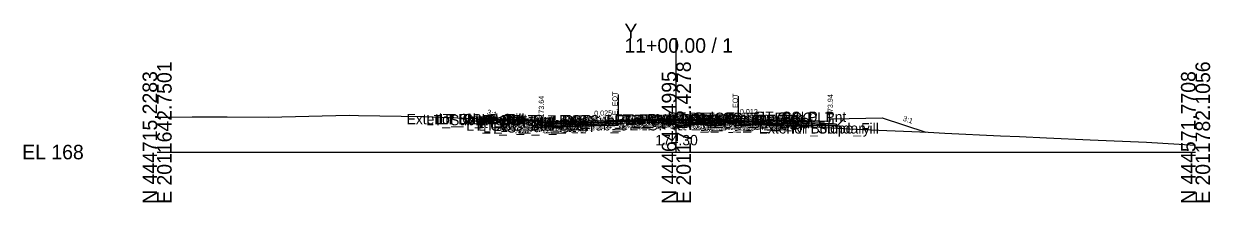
# Model space of a CAD drawing. Extents: x -26 to 3203, y -10 to 9532.
# Drawn here: x -25.7 to 202.8, y 4990.3 to 5024.8 of the extents above; entities that cross this region are included whole.
import ezdxf

# ---------------------------------------------------------------- set-up
doc = ezdxf.new("R2010")
doc.units = 0
for name, color, linetype in [('Default', 7, 'Continuous'), ('Exist CMT Pavement', 7, 'Continuous'), ('Exist Cross Section Cell', 7, 'Continuous'), ('Exist XS Center Line Elevation Label', 7, 'Continuous'), ('Exist XS Ground Line', 7, 'Continuous'), ('Prop CMT Conc Surface', 7, 'Continuous'), ('Prop CMT Concrete Structures', 7, 'Continuous'), ('Prop CMT Pvmt Course 1', 7, 'Continuous'), ('Prop CMT Pvmt Course 1 CG', 7, 'Continuous'), ('Prop CMT Pvmt Course 1 Wedge', 7, 'Continuous'), ('Prop CMT Pvmt Course 2', 7, 'Continuous'), ('Prop CMT Pvmt Course 2 Wedge', 7, 'Continuous'), ('Prop CMT Pvmt Course 3', 7, 'Continuous'), ('Prop CMT Pvmt Surface', 7, 'Continuous'), ('Prop CMT Pvmt Wedge Surface 1', 7, 'Continuous'), ('Prop CMT Pvmt Wedge Surface 2', 7, 'Continuous'), ('Prop CMT Pvmt Wedge Surface 3', 7, 'Continuous'), ('Prop CMT Slope Grass', 7, 'Continuous'), ('Prop CMT Subgrade Earthwork', 7, 'Continuous'), ('Prop XS Hydro Elevations', 7, 'Continuous'), ('Prop XS Label Text', 7, 'Continuous'), ('Prop XS SE Text', 7, 'Continuous'), ('Prop XS Side Slope Text', 7, 'Continuous'), ('Scratch_Level_0', 7, 'Continuous')]:
    doc.layers.add(name, color=color, linetype=linetype)

msp = doc.modelspace()

# ---------------------------------------------------------------- linework, layer by layer
at = {"layer": 'Exist CMT Pavement'}
msp.add_lwpolyline([(88.78, 5006.11), (89.34, 5006.15), (89.79, 5006.17), (90.87, 5006.19), (92.27, 5006.22), (94.36, 5006.26), (95.85, 5006.27), (97.83, 5006.28), (99.28, 5006.3), (100.22, 5006.31), (101.31, 5006.26), (102.91, 5006.2), (104.8, 5006.14), (105.66, 5006.11), (106.57, 5006.07), (107.47, 5006.02), (108.27, 5005.98), (110.14, 5005.9), (111.1, 5005.86), (111.94, 5005.78)], dxfattribs=at)
at = {"layer": 'Exist Cross Section Cell'}
for p, q in [((100, 5000), (100, 5021.96)), ((0, 5000), (100, 5000)), ((100, 5000), (200, 5000))]:
    msp.add_line(p, q, dxfattribs=at)
at = {"layer": 'Exist XS Ground Line'}
msp.add_lwpolyline([(0, 5006.71), (2.64, 5006.72), (6.76, 5006.78), (7.82, 5006.8), (13.47, 5006.8), (21.44, 5006.74), (36.96, 5007.1), (38.76, 5007.07), (51.13, 5006.87), (51.56, 5006.85), (64.13, 5006.35), (72.62, 5006.01), (73.31, 5006), (75.59, 5005.96), (78.67, 5005.98), (81.5, 5006.01), (86.68, 5006.09), (88.76, 5006.11), (89.34, 5006.15), (89.79, 5006.17), (90.87, 5006.19), (92.27, 5006.22), (94.36, 5006.26), (95.85, 5006.27), (97.83, 5006.28), (99.28, 5006.3), (100.22, 5006.31), (101.31, 5006.26), (102.91, 5006.2), (104.8, 5006.14), (105.66, 5006.11), (106.57, 5006.07), (107.47, 5006.02), (108.27, 5005.98), (110.14, 5005.9), (111.1, 5005.86), (111.95, 5005.77), (119.91, 5005.27), (123.03, 5005.08), (134.57, 5004.42), (137.39, 5004.29), (148.51, 5003.82), (151.74, 5003.67), (162.45, 5003.14), (166.09, 5003), (171.32, 5002.75), (179.7, 5002.39), (190.53, 5001.89), (200, 5001.32)], dxfattribs=at)
at = {"layer": 'Prop CMT Conc Surface'}
for points in [[(74, 5005.64), (74, 5006.14), (73.5, 5006.14)], [(76, 5005.77), (74, 5005.64)], [(127.65, 5006.04), (129.65, 5005.94)], [(129.65, 5005.94), (129.65, 5006.44), (130.15, 5006.44)]]:
    msp.add_lwpolyline(points, dxfattribs=at)
at = {"layer": 'Prop CMT Concrete Structures'}
for points in [[(76, 5005.77), (74, 5005.64), (74, 5006.14), (73.5, 5006.14)], [(73.5, 5006.14), (73.5, 5005.12), (76, 5005.18)], [(76, 5005.18), (76, 5005.77)], [(127.65, 5006.04), (129.65, 5005.94), (129.65, 5006.44), (130.15, 5006.44)], [(130.15, 5006.44), (130.15, 5005.43), (127.65, 5005.46)], [(127.65, 5005.46), (127.65, 5006.04)]]:
    msp.add_lwpolyline(points, dxfattribs=at)
at = {"layer": 'Prop CMT Pvmt Course 1'}
for points in [[(100, 5006.37), (76, 5005.77)], [(76, 5005.52), (88.76, 5005.83)], [(76, 5005.77), (76, 5005.52)], [(88.76, 5005.96), (100, 5006.24)], [(88.76, 5005.83), (88.76, 5005.96)], [(100, 5006.37), (127.65, 5006.04)], [(100, 5006.12), (100, 5006.37)], [(100, 5006.12), (100, 5006.37)], [(111.96, 5006.1), (100, 5006.24)], [(100, 5006.24), (100, 5006.12), (100, 5006.12)], [(100, 5006.24), (100, 5006.12), (100, 5006.12)], [(111.96, 5005.98), (111.96, 5006.1)], [(113.07, 5005.96), (111.96, 5005.98)], [(127.65, 5006.04), (127.65, 5005.79)]]:
    msp.add_lwpolyline(points, dxfattribs=at)
at = {"layer": 'Prop CMT Pvmt Course 1 CG'}
for points in [[(76, 5005.18), (73, 5005.11), (72.66, 5004.77)], [(76, 5004.85), (76, 5005.18)], [(127.65, 5005.46), (130.65, 5005.43), (130.99, 5005.09)], [(127.65, 5005.13), (127.65, 5005.46)], [(130.99, 5005.09), (127.65, 5005.13)], [(72.66, 5004.77), (76, 5004.85)]]:
    msp.add_lwpolyline(points, dxfattribs=at)
at = {"layer": 'Prop CMT Pvmt Course 1 Wedge'}
for points in [[(100, 5006.24), (88.76, 5005.96)], [(100, 5006.24), (111.96, 5006.1)]]:
    msp.add_lwpolyline(points, dxfattribs=at)
at = {"layer": 'Prop CMT Pvmt Course 2'}
for points in [[(88.76, 5005.83), (76, 5005.52)], [(76, 5005.52), (76, 5005.18)], [(76, 5005.18), (88.76, 5005.5)], [(88.76, 5005.5), (88.76, 5005.83)], [(111.96, 5005.64), (111.96, 5005.98)], [(111.96, 5005.98), (127.65, 5005.79)], [(113.07, 5005.63), (111.96, 5005.64)], [(127.65, 5005.79), (127.65, 5005.46)]]:
    msp.add_lwpolyline(points, dxfattribs=at)
at = {"layer": 'Prop CMT Pvmt Course 2 Wedge'}
msp.add_lwpolyline([(107.33, 5006.03), (111.96, 5005.98)], dxfattribs=at)
at = {"layer": 'Prop CMT Pvmt Course 3'}
for points in [[(88.76, 5005.5), (76, 5005.18)], [(76, 5005.18), (76, 5004.85)], [(76, 5004.85), (88.76, 5005.17)], [(88.76, 5005.17), (88.76, 5005.5)], [(111.96, 5005.64), (127.65, 5005.46)], [(111.96, 5005.31), (111.96, 5005.64)], [(127.65, 5005.13), (111.96, 5005.31)], [(127.65, 5005.46), (127.65, 5005.13)]]:
    msp.add_lwpolyline(points, dxfattribs=at)
at = {"layer": 'Prop CMT Pvmt Surface'}
for points in [[(100, 5006.37), (76, 5005.77)], [(100, 5006.37), (127.65, 5006.04)]]:
    msp.add_lwpolyline(points, dxfattribs=at)
at = {"layer": 'Prop CMT Pvmt Wedge Surface 1'}
for points in [[(88.76, 5005.83), (76, 5005.52)], [(76, 5005.52), (76, 5005.77)], [(100, 5006.24), (88.76, 5005.96)], [(88.76, 5005.96), (88.76, 5005.83)], [(100, 5006.24), (111.96, 5006.1)], [(111.96, 5006.1), (111.96, 5005.98)], [(111.96, 5005.98), (113.07, 5005.96)], [(127.65, 5005.79), (127.65, 5006.04)]]:
    msp.add_lwpolyline(points, dxfattribs=at)
at = {"layer": 'Prop CMT Pvmt Wedge Surface 2'}
for points in [[(100, 5006.12), (76, 5005.52)], [(76, 5005.52), (76, 5005.77)], [(100, 5006.12), (113.07, 5005.96)], [(127.65, 5005.79), (127.65, 5006.04)]]:
    msp.add_lwpolyline(points, dxfattribs=at)
at = {"layer": 'Prop CMT Pvmt Wedge Surface 3'}
for points in [[(100, 5005.78), (76, 5005.18)], [(76, 5005.18), (76, 5005.77)], [(100, 5005.78), (113.07, 5005.63)], [(127.65, 5005.46), (127.65, 5006.04)]]:
    msp.add_lwpolyline(points, dxfattribs=at)
at = {"layer": 'Prop CMT Slope Grass'}
for points in [[(73.5, 5006.14), (64, 5006.33), (63.89, 5006.36)], [(73.5, 5006.14), (64, 5006.33), (63.89, 5006.36)], [(130.15, 5006.44), (139.65, 5006.63), (148.04, 5003.84)]]:
    msp.add_lwpolyline(points, dxfattribs=at)
at = {"layer": 'Prop CMT Subgrade Earthwork'}
for points in [[(76, 5004.85), (72.66, 5004.77), (71.24, 5006.18)], [(88.76, 5005.17), (76, 5004.85)], [(88.76, 5005.17), (88.78, 5006.11)], [(111.96, 5005.31), (111.94, 5005.78)], [(111.96, 5005.31), (127.65, 5005.13)], [(127.65, 5005.13), (130.99, 5005.09), (132.39, 5006.49)]]:
    msp.add_lwpolyline(points, dxfattribs=at)
at = {"layer": 'Prop XS Label Text'}
for p, q in [((88.78, 5011.11), (88.78, 5006.11)), ((111.94, 5010.78), (111.94, 5005.78))]:
    msp.add_line(p, q, dxfattribs=at)

# ---------------------------------------------------------------- texts
at = {"layer": 'Default'}
msp.add_text('-', height=0.0001, dxfattribs=at).set_placement((0, 5000))
at = {"layer": 'Exist Cross Section Cell'}
for s, p in [('Y', (90, 5021.96)), ('11+00.00 / 1', (90, 5019.16)), ('EL 168', (-26, 4998.6))]:
    msp.add_text(s, height=2.8, dxfattribs=at).set_placement(p)
for s, p in [('E 2011642.7501', (2.8, 4990)), ('E 2011712.4278', (102.8, 4990)), ('E 2011782.1056', (202.8, 4990)), ('N 444715.2283', (0, 4990)), ('N 444643.4995', (100, 4990)), ('N 444571.7708', (200, 4990))]:
    msp.add_text(s, height=2.8, rotation=90, dxfattribs=at).set_placement(p)
at = {"layer": 'Exist XS Center Line Elevation Label'}
msp.add_text('174.30', height=2, dxfattribs=at).set_placement((95.95, 5001.3))
msp.add_text('174.30', height=2, dxfattribs=at).set_placement((95.95, 5001.3))
at = {"layer": 'Prop XS Hydro Elevations'}
for s, p in [('173.64', (74.5, 5006.64)), ('173.94', (130.15, 5006.94))]:
    msp.add_text(s, height=1, rotation=90, dxfattribs=at).set_placement(p)
at = {"layer": 'Prop XS Label Text'}
for p in [(88.68, 5007.13), (111.84, 5006.8)]:
    msp.add_text('E. EOT', height=1, rotation=90, dxfattribs=at).set_placement(p)
at = {"layer": 'Prop XS SE Text'}
for s, rotation, p in [('0.025', 1.4321, (84.19, 5006.97)), ('0.012', 359.335, (112.23, 5007.31))]:
    msp.add_text(s, height=1, rotation=rotation, dxfattribs=at).set_placement(p)
at = {"layer": 'Prop XS Side Slope Text'}
for p in [(63.43, 5007.31), (63.43, 5007.31), (143.56, 5006.06)]:
    msp.add_text('3:1', height=1, rotation=341.5651, dxfattribs=at).set_placement(p)
at = {"layer": 'Scratch_Level_0'}
for s, p in [('Exterior Boundary', (48.04, 5005.36)), ('LT_Sub_Trench_Out_DLT', (51.81, 5005.18)), ('LT_Slope_Cut', (53.53, 5005.36)), ('LT_CSLP_Pnt', (54.17, 5005.33)), ('LT_Slope_Fill', (54.41, 5005.36)), ('LT_CG_Top_Face', (61.26, 5005.14)), ('LT_CG_Top_BOC', (61.78, 5005.14)), ('LT_PV_Sub_Tie_Out', (73.72, 5005.11)), ('RT_PV_IEEOP_EG', (88.14, 5005.3)), ('LT_PV_IEEOP_EG', (88.19, 5005.3)), ('RT_PV1_IEEOP', (90.47, 5005.24)), ('LT_PV1_IEEOP', (90.52, 5005.24)), ('PV1_PGL', (94.47, 5005.37)), ('RT_Sub_Trench_Out_DLT', (98.32, 5005.66)), ('RT_CG_Top_Face', (102.28, 5005.61)), ('RT_PV1_OEOT', (103.76, 5005.21)), ('RT_CG_Top_BOC', (103.8, 5005.61)), ('RT_CSLP_Pnt', (115.19, 5005.8)), ('LT_CG1_Shelf_Out', (59.55, 5004.11)), ('LT_CG_Bot_BOC', (61.81, 5004.12)), ('LT_CG_Top_Gut', (62.24, 5004.64)), ('LT_Sub_OEOP', (62.77, 5003.77)), ('LT_CG_Bot_IE', (65.91, 5004.18)), ('LT_Sub_OEOT', (66.08, 5003.85)), ('LT_PV2_OEOT', (66.17, 5004.52)), ('LT_PV3_OEOT', (66.17, 5004.18)), ('LT_PV1_OEOT', (66.74, 5004.77)), ('LT_PV_OEEOP_EG', (76.31, 5005.11)), ('LT_Sub_OEEOP', (77.98, 5004.17)), ('LT_PV2_OEEOP', (78.07, 5004.83)), ('LT_PV3_OEEOP', (78.07, 5004.5)), ('LT_PV1_OEEOP', (78.64, 5004.96)), ('RT_PV2_IEEOP', (89.91, 5005.12)), ('RT_PV3_IEEOP', (89.91, 5004.78)), ('LT_PV2_IEEOP', (89.95, 5005.12)), ('LT_PV3_IEEOP', (89.95, 5004.78)), ('PV2_PGL', (93.91, 5005.12)), ('RT_PV_Sub_Tie_Out', (96.84, 5004.78)), ('RT_PV_OEEOP_EG', (99.45, 5004.77)), ('RT_Sub_OEEOP', (101.12, 5004.31)), ('RT_PV2_OEEOP', (101.22, 5004.98)), ('RT_PV3_OEEOP', (101.22, 5004.64)), ('RT_PV1_OEEOP', (101.78, 5005.1)), ('RT_CG1_Shelf_Out', (102.57, 5004.6)), ('RT_CG_Bot_IE', (102.93, 5004.63)), ('RT_Sub_OEOT', (103.1, 5004.3)), ('RT_PV2_OEOT', (103.19, 5004.96)), ('RT_PV3_OEOT', (103.19, 5004.63)), ('RT_CG_Top_Gut', (103.26, 5005.11)), ('RT_CG_Bot_BOC', (103.84, 5004.6)), ('RT_Sub_OEOP', (106.47, 5004.26)), ('Exterior Boundary', (115.87, 5003.58)), ('RT_Slope_Fill', (122.2, 5003.58))]:
    msp.add_text(s, height=2, dxfattribs=at).set_placement(p)

doc.saveas('drawing.dxf')
